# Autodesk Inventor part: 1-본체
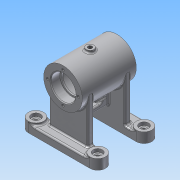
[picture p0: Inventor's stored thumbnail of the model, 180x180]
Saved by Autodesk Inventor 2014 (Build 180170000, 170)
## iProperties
Created: 2015-11
Part Number: 1-본체
Material: 알루미늄 6061
Document SubType Name: Modeling
Designer: 103-23
Density: 2.71 g/cm^3
Appearance: 알루미늄 - 평지
Mass: 358.984 g
Surface Area: 460.1 cm^2
Volume: 132.467 cm^3
Author: 103-23
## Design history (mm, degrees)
sketch "스케치1"
  geometry: L1 (-40, 40)-(40, 40); L2 (40, 20)-(-40, 20); A1 r 10 centre (40, 30) between (40, 20) and (40, 40); A2 r 10 centre (-40, 30) between (-40, 40) and (-40, 20); 1 further point
  constraints: 4 end point, 4 point on circle, 4 tangent, 2 centre point, 1 horizontal, 1 parallel
  dimensions: "d0" = 40 distance from line of L1 point (0, 0); "d1" = 20 distance between parallel lines of L2 L1; "d2" = 80 distance of A1.centre A2.centre; "d3" = 40 horizontal distance of point (0, 0) A2.centre
extrude "돌출1" new body sketch "스케치1" distance "d4" = 10; taper "d5" = 0 deg
node "작업 평면1"
sketch "스케치2"
  geometry: L1 (-35, 68)-(35, 68); L2 (-35, 84)-(-23, 84); L3 (-23, 84)-(-23, 82); L4 (-23, 82)-(-21, 82); L5 (-21, 82)-(-21, 89); L6 (-21, 89)-(21, 89); L7 (21, 89)-(21, 82); L8 (21, 82)-(23, 82); L9 (23, 82)-(23, 84); L10 (23, 84)-(35, 84); L11 (35, 84)-(35, 93); L12 (35, 93)-(-35, 93); L13 (-35, 93)-(-35, 84); 2 further points
  constraints: 26 end point, 10 parallel, 5 collinear, 2 point on line, 1 horizontal, 1 midpoint, 1 perpendicular, 1 vertical alignment
  dimensions: "d7" = 70 distance of L1.start L1.end; "d8" = 68 distance from line of point (0, 0) L1; "d9" = 28 diameter of L4.end L1; "d10" = 32 diameter of L2 L1; "d11" = 42 diameter of L6 L1; "d12" = 50 diameter of L12 L1; "d13" = 12 distance of L2.start L2.end; "d14" = 42 distance of L5.end L6.end
revolve "회전1" sketch "스케치2" stored, may be unused: angle "d15" = 90 deg
sketch "스케치3"
  geometry: L1 (0, 20)-(80, 20) reference; L2 (15, 12)-(65, 12); L3 (65, 12)-(65, 20); L4 (65, 20)-(15, 20); L5 (15, 20)-(15, 12); L6 (15, 12)-(65, 20); L7 (65, 12)-(15, 20); 3 further points
  constraints: 12 end point, 3 midpoint, 2 parallel, 1 collinear, 1 horizontal, 1 perpendicular, 1 vertical alignment
  dimensions: "d17" = 8 distance between parallel lines of L2 L4; "d18" = 50 distance of L2.start L2.end
extrude "돌출2" join sketch "스케치3" stored distance "d19" = 10; taper "d20" = 0 deg
node "작업 평면2"
sketch "스케치4"
  geometry: L1 (-20, 23)-(20, 23); L2 (20, 23)-(20, 45.656); L3 (-20, 45.656)-(-20, 23); L4 (-20, 23)-(20, 43); L5 (20, 23)-(-20, 43); L6 (35, 43)-(-35, 43) reference; L7 (20, 10)-(20, 68) reference; L8 (-20, 10)-(-20, 68) reference; L9 (-20, 45.656)-(20, 45.656); 3 further points
  constraints: 12 end point, 4 point on line, 3 midpoint, 2 perpendicular, 1 collinear, 1 horizontal, 1 parallel, 1 vertical alignment
  dimensions: "d25" = 20 distance between parallel lines of L6 L1; "d26" = 22.65606 distance between parallel lines of L9 L1
extrude "돌출3" join sketch "스케치4" stored distance "d23" = 8; taper "d24" = 0 deg
sketch "스케치5"
  geometry: L1 (43.322, -20)-(23, -20) reference; L2 (36.5, 8)-(36.5, -8); L3 (29.5, -8)-(29.5, 8); A1 r 3.5 centre (33, -8) between (29.5, -8) and (36.5, -8); A2 r 3.5 centre (33, 8) between (36.5, 8) and (29.5, 8); 2 further points
  constraints: 4 end point, 4 point on circle, 4 tangent, 2 centre point, 2 perpendicular, 1 horizontal alignment, 1 midpoint
  dimensions: "d27" = 33 horizontal distance of A1.centre point (0, 0); "d28" = 3.5 radius of A1; "d29" = 23 dimension on A1 A2
extrude "돌출4" cut sketch "스케치5" stored distance "d30" = 8; taper "d31" = 0 deg
sketch "스케치6"
  geometry: C1 r 10 at (-40, 30); C2 r 10 at (40, 30); A1 r 10 centre (40, 30) between (40, 20) and (40, 40) reference; A2 r 10 centre (-40, 30) between (-40, 40) and (-40, 20) reference; 1 further point
  constraints: 2 centre point, 2 coincident, 2 concentric
extrude "돌출5" join sketch "스케치6" distance "d32" = 3; taper "d33" = 0 deg
hole "구멍1" diameter "d36" = 6; stored, may be unused: countersink angle "d40" = 90 deg, drill point angle "d42" = 118 deg; dims "d34" = 10, "d35" = 10, "d37" = 6, "d38" = 12, "d39" = 4, "d41" = 8
hole "구멍2" diameter "d45" = 6; stored, may be unused: countersink angle "d49" = 90 deg, drill point angle "d51" = 118 deg; dims "d43" = 10, "d44" = 10, "d46" = 6, "d47" = 12, "d48" = 4, "d50" = 8
node "작업 평면3"
sketch "스케치7"
  geometry: C1 r 5 at (0, 0); 1 further point
  constraints: 1 centre point, 1 coincident
  dimensions: "d53" = 10 diameter of C1
extrude "돌출6" join sketch "스케치7" stored distance "d54" = 3; taper "d55" = 0 deg
hole "구멍3" diameter "d58" = 5.188; stored, may be unused: countersink angle "d62" = 90 deg, drill point angle "d64" = 118 deg; dims "d56" = 10, "d57" = 10, "d59" = 6, "d60" = 12, "d61" = 4, "d63" = 8
node "작업 평면4"
sketch "스케치8"
  geometry: L1 (-14, 68)-(14, 68); L2 (0, 68)-(-14, 43.751); L3 (0, 82)-(0, 54); A1 r 14 centre (0, 68) between (-14, 68) and (14, 68) reference; 1 further point
  constraints: 6 end point, 4 point on circle, 2 midpoint, 1 coincident, 1 horizontal, 1 perpendicular
  dimensions: "d66" = 28 distance of L2.start L2.end; "d104" = 30 deg angle of L3 L2
node "작업 평면5"
sketch "스케치9"
  geometry: C1 r 6 at (0, 0); 2 further points
  constraints: 1 centre point, 1 coincident
  dimensions: "d68" = 12 diameter of C1
extrude "돌출7" join sketch "스케치9" stored distance "d69" = 3; taper "d70" = 0 deg
hole "구멍4" diameter "d73" = 5.188; stored, may be unused: countersink angle "d77" = 90 deg, drill point angle "d79" = 118 deg; dims "d71" = 10, "d72" = 10, "d74" = 6, "d75" = 12, "d76" = 4, "d78" = 8
sketch "스케치10"
  geometry: C1 r 25 at (0, 0) reference; C2 r 16 at (0, 0) reference; A1 r 20 centre (0, 0) between (0, 20) and (0, -20); 3 further points
  constraints: 4 point on circle, 2 horizontal alignment, 2 vertical alignment, 1 centre point, 1 coincident
  dimensions: "d80" = 40 diameter of A1
hole "구멍5" sketch "스케치10" at (0, 20), (0, -20), (20, 0), (-20, 0) diameter "d81" = 3.242; stored, may be unused: countersink angle "d85" = 90 deg, drill point angle "d87" = 118 deg; dims "d82" = 8, "d83" = 12, "d84" = 4, "d86" = 10
node "작업 평면6"
sketch "스케치11"
  geometry: L1 (35, 25)-(-35, 25) reference; L2 (-35, 25)-(-35, -25) reference; 2 further points
  constraints: 1 other
  dimensions: "d88" = 35 distance from line of L2 point (0, 0); "d89" = 25 distance from line of L1 point (0, 0)
feature "엠보싱1" sketch "스케치11" dims "d0" = 40, "d1" = 20, "d2" = 80, "d3" = 40, "d7" = 70, "d8" = 68, "d9" = 28, "d10" = 32, "d11" = 42, "d12" = 50, "d13" = 12, "d14" = 42, "d90" = 0.5, "d91" = 0
fillet "모깎기1" dims "d92" = 0.3, "d93" = 3, "d96" = 2
fillet "모깎기2" dims "d94" = 2
fillet "모깎기5" dims "d98" = 2
fillet "모깎기6" dims "d99" = 2
fillet "모깎기7" dims "d100" = 2
chamfer "모따기1" distance "d101" = 1; stored, may be unused: second distance "d102" = 2, angle "d103" = 45 deg
node "솔리드1"
mirror "대칭1"
mirror "대칭2"
mirror "대칭3"
mirror "대칭4"
other parameters: "d6" = 0, "d21" = 0, "d52" = -96, "d65" = 0
